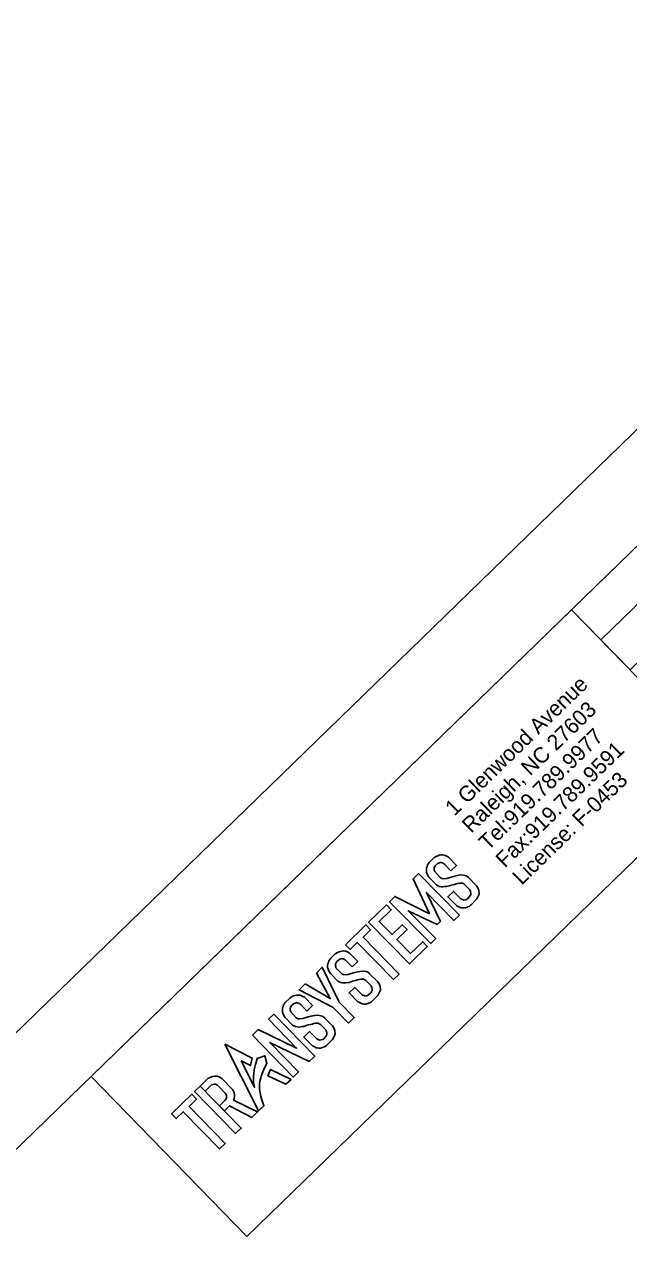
# Model space of a CAD drawing. Extents: x 2010880 to 2012866, y 442935 to 444909.
# Drawn here: x 2011791.8 to 2011972, y 444542.2 to 444908.8 of the extents above; entities that cross this region are included whole.
import ezdxf

# ---------------------------------------------------------------- set-up
doc = ezdxf.new("R2010")
doc.units = 0
for name, color, linetype in [('Old_Level_1', 7, 'Continuous'), ('Old_Level_2', 7, 'Continuous'), ('Old_Level_58', 7, 'Continuous'), ('Sheet Plan And Profile CELL', 7, 'Continuous'), ('Sheet Plot Border Outside CELL', 7, 'Continuous')]:
    doc.layers.add(name, color=color, linetype=linetype)

msp = doc.modelspace()

# ---------------------------------------------------------------- linework, layer by layer
at = {"layer": 'Old_Level_1'}
for points in [[(2011919.06, 444655.93), (2011920.72, 444657.54), (2011918.29, 444660.03), (2011917.66, 444660.4), (2011917.05, 444660.63), (2011916.56, 444660.7), (2011916.05, 444660.69), (2011915.54, 444660.59), (2011915.11, 444660.42), (2011915.11, 444660.42), (2011914.65, 444660.24), (2011914.21, 444659.99), (2011913.93, 444659.82), (2011912.7, 444658.58), (2011912.38, 444658.14), (2011912.11, 444657.77), (2011911.95, 444657.28), (2011911.81, 444656.84), (2011911.72, 444656.36), (2011911.72, 444655.92), (2011911.8, 444655.49), (2011911.93, 444655.07), (2011912.24, 444654.4), (2011912.56, 444653.99), (2011914.77, 444651.72), (2011915.18, 444651.46), (2011915.69, 444651.26), (2011916.19, 444651.17), (2011916.61, 444651.16), (2011917.18, 444651.22), (2011917.75, 444651.29), (2011918.1, 444651.33), (2011918.61, 444651.5), (2011919.11, 444651.68), (2011919.57, 444651.77), (2011920.08, 444651.87), (2011920.65, 444652.05), (2011921.11, 444652.19), (2011921.64, 444652.27), (2011922.07, 444652.27), (2011922.41, 444652.27), (2011922.86, 444652.04), (2011923.13, 444651.89), (2011924.67, 444650.26), (2011924.89, 444649.8), (2011925.01, 444649.33), (2011924.97, 444648.89), (2011924.83, 444648.53), (2011924.64, 444648.24), (2011923.96, 444647.56), (2011923.67, 444647.4), (2011923.3, 444647.3), (2011922.93, 444647.21), (2011922.59, 444647.35), (2011922.25, 444647.5), (2011921.99, 444647.61), (2011919.79, 444649.81), (2011918.13, 444648.16), (2011920.75, 444645.54), (2011921.03, 444645.42), (2011921.83, 444644.99), (2011922.16, 444644.9), (2011922.56, 444644.85), (2011923.09, 444644.84), (2011923.45, 444644.92), (2011923.89, 444645.09), (2011924.05, 444645.15), (2011924.48, 444645.32), (2011924.9, 444645.66), (2011925.21, 444645.9), (2011926.71, 444647.43), (2011927.03, 444647.95), (2011927.37, 444648.79), (2011927.48, 444649.08), (2011927.37, 444650.08), (2011927.06, 444650.88), (2011926.68, 444651.49), (2011924.26, 444653.91), (2011923.92, 444654.24), (2011923.57, 444654.42), (2011923.18, 444654.54), (2011922.27, 444654.71), (2011921.37, 444654.61), (2011920.27, 444654.35), (2011919.42, 444654.15), (2011917.84, 444653.68), (2011916.91, 444653.56), (2011916.38, 444653.63), (2011916.13, 444653.78), (2011915.87, 444653.93), (2011914.21, 444655.7), (2011914.12, 444655.97), (2011914.03, 444656.24), (2011914.05, 444656.47), (2011914.08, 444656.78), (2011914.19, 444657.03), (2011914.3, 444657.29), (2011914.43, 444657.37), (2011914.39, 444657.44), (2011915.09, 444658.09), (2011915.36, 444658.21), (2011915.64, 444658.32), (2011915.91, 444658.44), (2011916.14, 444658.39), (2011916.47, 444658.32), (2011916.73, 444658.19), (2011916.98, 444658.05), (2011917.19, 444657.83)], [(2011912.63, 444643.14), (2011902.29, 444648.31), (2011900.77, 444646.69), (2011913.01, 444634.23), (2011914.51, 444635.71), (2011906.33, 444644.04), (2011914.94, 444639.88), (2011915.93, 444640.79), (2011911.76, 444649.48), (2011919.97, 444641.11), (2011921.6, 444642.7), (2011909.4, 444655.14), (2011907.76, 444653.54)], [(2011899.78, 444645.77), (2011894.49, 444640.62), (2011906.65, 444628.14), (2011912, 444633.35), (2011910.63, 444634.76), (2011907.02, 444631.24), (2011902.94, 444635.43), (2011905.96, 444638.37), (2011904.51, 444639.85), (2011901.47, 444636.89), (2011897.63, 444640.83), (2011901.22, 444644.32)], [(2011887.55, 444633.87), (2011893.61, 444639.77), (2011895.06, 444638.29), (2011892.83, 444636.12), (2011903.59, 444625.07), (2011901.91, 444623.43), (2011891.08, 444634.55), (2011888.95, 444632.48)], [(2011889.6, 444627.23), (2011891.25, 444628.84), (2011888.83, 444631.33), (2011888.2, 444631.7), (2011887.58, 444631.93), (2011887.1, 444632), (2011886.59, 444631.99), (2011886.07, 444631.89), (2011885.65, 444631.72), (2011885.65, 444631.72), (2011885.18, 444631.54), (2011884.75, 444631.29), (2011884.47, 444631.12), (2011883.24, 444629.87), (2011882.92, 444629.44), (2011882.65, 444629.07), (2011882.49, 444628.57), (2011882.34, 444628.14), (2011882.26, 444627.66), (2011882.26, 444627.22), (2011882.34, 444626.79), (2011882.47, 444626.37), (2011882.78, 444625.69), (2011883.1, 444625.29), (2011885.31, 444623.02), (2011885.72, 444622.76), (2011886.23, 444622.56), (2011886.72, 444622.47), (2011887.15, 444622.45), (2011887.72, 444622.52), (2011888.29, 444622.58), (2011888.64, 444622.62), (2011889.15, 444622.8), (2011889.65, 444622.98), (2011890.1, 444623.07), (2011890.62, 444623.17), (2011891.19, 444623.35), (2011891.65, 444623.49), (2011892.18, 444623.56), (2011892.6, 444623.57), (2011892.95, 444623.57), (2011893.39, 444623.33), (2011893.67, 444623.19), (2011895.2, 444621.56), (2011895.43, 444621.1), (2011895.54, 444620.63), (2011895.51, 444620.19), (2011895.37, 444619.83), (2011895.17, 444619.54), (2011894.5, 444618.85), (2011894.2, 444618.69), (2011893.83, 444618.6), (2011893.46, 444618.51), (2011893.13, 444618.65), (2011892.79, 444618.79), (2011892.53, 444618.91), (2011890.33, 444621.11), (2011888.67, 444619.46), (2011891.29, 444616.83), (2011891.57, 444616.71), (2011892.36, 444616.28), (2011892.7, 444616.2), (2011893.1, 444616.14), (2011893.63, 444616.14), (2011893.98, 444616.21), (2011894.42, 444616.39), (2011894.58, 444616.45), (2011895.02, 444616.62), (2011895.44, 444616.95), (2011895.75, 444617.2), (2011897.24, 444618.73), (2011897.57, 444619.25), (2011897.9, 444620.09), (2011898.02, 444620.37), (2011897.91, 444621.38), (2011897.6, 444622.17), (2011897.22, 444622.79), (2011894.79, 444625.21), (2011894.46, 444625.54), (2011894.1, 444625.72), (2011893.72, 444625.84), (2011892.8, 444626.01), (2011891.91, 444625.91), (2011890.8, 444625.65), (2011889.96, 444625.45), (2011888.38, 444624.98), (2011887.45, 444624.85), (2011886.92, 444624.93), (2011886.66, 444625.08), (2011886.41, 444625.23), (2011884.75, 444627), (2011884.66, 444627.27), (2011884.57, 444627.54), (2011884.59, 444627.77), (2011884.62, 444628.07), (2011884.73, 444628.33), (2011884.84, 444628.59), (2011884.97, 444628.67), (2011884.93, 444628.73), (2011885.63, 444629.39), (2011885.9, 444629.51), (2011886.18, 444629.62), (2011886.45, 444629.74), (2011886.68, 444629.69), (2011887.01, 444629.62), (2011887.26, 444629.48), (2011887.52, 444629.35), (2011887.73, 444629.13)], [(2011875.55, 444622.17), (2011873.73, 444620.39), (2011883.91, 444615.12), (2011888.5, 444610.45), (2011890.2, 444612.12), (2011885.65, 444616.75), (2011880.63, 444627.16), (2011878.89, 444625.38), (2011883.05, 444617.79)], [(2011876.08, 444614.06), (2011877.74, 444615.67), (2011875.31, 444618.16), (2011874.68, 444618.53), (2011874.07, 444618.76), (2011873.58, 444618.83), (2011873.07, 444618.82), (2011872.56, 444618.72), (2011872.13, 444618.55), (2011872.13, 444618.55), (2011871.67, 444618.37), (2011871.23, 444618.12), (2011870.95, 444617.95), (2011869.72, 444616.71), (2011869.4, 444616.27), (2011869.13, 444615.9), (2011868.97, 444615.4), (2011868.83, 444614.97), (2011868.74, 444614.49), (2011868.74, 444614.05), (2011868.82, 444613.62), (2011868.95, 444613.2), (2011869.26, 444612.52), (2011869.58, 444612.12), (2011871.79, 444609.85), (2011872.2, 444609.59), (2011872.71, 444609.39), (2011873.21, 444609.3), (2011873.63, 444609.28), (2011874.2, 444609.35), (2011874.77, 444609.41), (2011875.12, 444609.46), (2011875.63, 444609.63), (2011876.13, 444609.81), (2011876.59, 444609.9), (2011877.1, 444610), (2011877.67, 444610.18), (2011878.13, 444610.32), (2011878.66, 444610.39), (2011879.09, 444610.4), (2011879.43, 444610.4), (2011879.88, 444610.16), (2011880.15, 444610.02), (2011881.69, 444608.39), (2011881.91, 444607.93), (2011882.03, 444607.46), (2011881.99, 444607.02), (2011881.85, 444606.66), (2011881.66, 444606.37), (2011880.98, 444605.68), (2011880.69, 444605.52), (2011880.32, 444605.43), (2011879.95, 444605.34), (2011879.61, 444605.48), (2011879.27, 444605.62), (2011879.01, 444605.74), (2011876.81, 444607.94), (2011875.15, 444606.29), (2011877.77, 444603.66), (2011878.05, 444603.54), (2011878.85, 444603.11), (2011879.18, 444603.03), (2011879.58, 444602.97), (2011880.11, 444602.97), (2011880.47, 444603.04), (2011880.91, 444603.22), (2011881.07, 444603.28), (2011881.5, 444603.45), (2011881.92, 444603.78), (2011882.23, 444604.03), (2011883.73, 444605.56), (2011884.05, 444606.08), (2011884.39, 444606.92), (2011884.5, 444607.21), (2011884.39, 444608.21), (2011884.08, 444609), (2011883.7, 444609.62), (2011881.28, 444612.04), (2011880.94, 444612.37), (2011880.59, 444612.55), (2011880.2, 444612.67), (2011879.29, 444612.84), (2011878.39, 444612.74), (2011877.29, 444612.48), (2011876.44, 444612.28), (2011874.86, 444611.81), (2011873.93, 444611.68), (2011873.4, 444611.76), (2011873.15, 444611.91), (2011872.89, 444612.06), (2011871.23, 444613.83), (2011871.14, 444614.1), (2011871.05, 444614.37), (2011871.07, 444614.6), (2011871.1, 444614.9), (2011871.21, 444615.16), (2011871.32, 444615.42), (2011871.45, 444615.5), (2011871.41, 444615.57), (2011872.11, 444616.22), (2011872.38, 444616.34), (2011872.66, 444616.45), (2011872.93, 444616.57), (2011873.16, 444616.52), (2011873.49, 444616.45), (2011873.75, 444616.31), (2011874, 444616.18), (2011874.21, 444615.96)], [(2011859.81, 444606.84), (2011871.99, 444594.34), (2011873.59, 444595.9), (2011865.02, 444604.69), (2011876.79, 444598.98), (2011878.39, 444600.56), (2011866.17, 444613.1), (2011864.61, 444611.58), (2011872.97, 444603), (2011861.49, 444608.49)], [(2011851.58, 444604.16), (2011861.67, 444584.22), (2011863.26, 444585.78), (2011862.92, 444586.62), (2011862.52, 444587.85), (2011862.31, 444588.52), (2011862.2, 444589.16), (2011862.05, 444590.07), (2011861.95, 444590.64), (2011861.95, 444591.18), (2011861.95, 444591.73), (2011861.95, 444592.43), (2011862.06, 444592.9), (2011862.13, 444593.43), (2011862.3, 444594.05), (2011862.46, 444594.6), (2011862.93, 444595.85), (2011863.36, 444596.84), (2011864.15, 444598.39), (2011863.47, 444600.72), (2011861.25, 444599.89), (2011860.7, 444598.11), (2011860.34, 444596.5), (2011860.19, 444595.25), (2011860.11, 444594.58), (2011860.12, 444593.8), (2011860.14, 444593.02), (2011860.15, 444592.44), (2011860.33, 444591.71), (2011860.43, 444591.31), (2011856.47, 444599.15), (2011859.2, 444597.77), (2011859.69, 444599.99)], [(2011845.66, 444590.13), (2011847.37, 444591.79), (2011847.62, 444591.97), (2011848.02, 444592.13), (2011848.41, 444592.2), (2011848.77, 444592.17), (2011849.11, 444592.04), (2011849.37, 444591.94), (2011849.78, 444591.52), (2011851.52, 444589.75), (2011851.71, 444589.47), (2011851.96, 444589.09), (2011852.07, 444588.79), (2011852.1, 444588.46), (2011852.06, 444588.12), (2011851.86, 444587.72), (2011851.66, 444587.46), (2011851.45, 444587.2), (2011849.95, 444585.72), (2011851.43, 444584.22), (2011852.93, 444585.7), (2011859.62, 444582.22), (2011861.34, 444583.92), (2011854.18, 444587.47), (2011854.36, 444587.84), (2011854.47, 444588.5), (2011854.44, 444589.22), (2011854.25, 444589.91), (2011853.96, 444590.52), (2011853.82, 444590.64), (2011850.67, 444593.94), (2011850, 444594.34), (2011849.27, 444594.57), (2011848.65, 444594.62), (2011847.82, 444594.48), (2011847.17, 444594.16), (2011846.53, 444593.85), (2011846.24, 444593.57), (2011844.21, 444591.62)], [(2011864.4, 444594.72), (2011865.24, 444596.61), (2011871.35, 444593.57), (2011869.79, 444592.16)], [(2011842.55, 444590.01), (2011844.21, 444591.62), (2011856.46, 444579.04), (2011854.8, 444577.42)], [(2011835.65, 444583.3), (2011841.71, 444589.21), (2011843.16, 444587.73), (2011840.93, 444585.55), (2011851.69, 444574.51), (2011850.01, 444572.87), (2011839.17, 444583.99), (2011837.05, 444581.92)]]:
    msp.add_lwpolyline(points, close=True, dxfattribs=at)
at = {"layer": 'Old_Level_58'}
msp.add_lwpolyline([(2011811.65, 444594.51), (2011955.07, 444733.97), (2012001.57, 444686.16), (2011858.15, 444546.7)], close=True, dxfattribs=at)
at = {"layer": 'Sheet Plan And Profile CELL'}
msp.add_line((2011963.82, 444724.98), (2012107.25, 444864.44), dxfattribs=at)
for points in [[(2012098.5, 444873.44), (2011023.1, 443827.72), (2011755.1, 443074.95), (2012830.5, 444120.66)], [(2011955.07, 444733.97), (2012098.5, 444873.44), (2012115.96, 444855.48), (2011972.54, 444716.02)]]:
    msp.add_lwpolyline(points, close=True, dxfattribs=at)
at = {"layer": 'Sheet Plot Border Outside CELL'}
msp.add_lwpolyline([(2011647.06, 442935.02), (2012865.85, 444120.17), (2012098.99, 444908.79), (2010880.21, 443723.65)], close=True, dxfattribs=at)

# ---------------------------------------------------------------- texts
at = {"layer": 'Old_Level_2'}
for s, p in [('1 Glenwood Avenue', (2011920.1, 444672.11)), ('Raleigh, NC 27603', (2011925.11, 444666.96)), ('Tel:919.789.9977 ', (2011930.13, 444661.8)), ('Fax:919.789.9591', (2011935.15, 444656.64)), ('License: F-0453', (2011940.16, 444651.48))]:
    msp.add_text(s, height=4.6576, rotation=44.1983, dxfattribs=at).set_placement(p)

doc.saveas('drawing.dxf')
